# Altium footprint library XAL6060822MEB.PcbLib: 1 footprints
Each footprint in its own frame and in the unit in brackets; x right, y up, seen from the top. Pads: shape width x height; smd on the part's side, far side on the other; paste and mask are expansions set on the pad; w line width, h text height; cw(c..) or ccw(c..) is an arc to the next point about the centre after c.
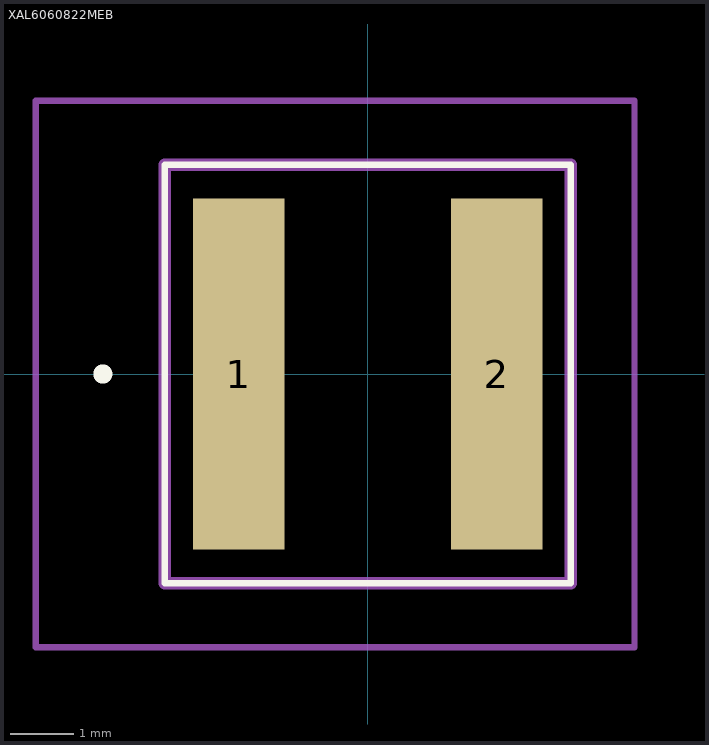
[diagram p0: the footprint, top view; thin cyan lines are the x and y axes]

## XAL6060822MEB [mm]
pads (2):
  rect 1.43x5.5 smd: 1(-2.02,0) 2(2.02,0)
Top Overlay:
  lines w0.1: -3.18,-3.28 3.18,-3.28 3.18,3.28 -3.18,3.28 -3.18,-3.28
  lines w0.2: -4.2,0 -4.2,0 ; -4.2,0 ccw(c-4.15,0) -4.1,0 ; -4.2,0 cw(c-4.15,0) -4.1,0 ; -4.2,0 -4.2,0 ; -4.2,0 ccw(c-4.15,0) -4.1,0 ; -4.1,0 -4.1,0
Mechanical 15:
  lines w0.2: -3.18,-3.28 3.18,-3.28 3.18,3.28 -3.18,3.28 -3.18,-3.28
Mechanical 20:
  lines w0.1: -5.2,-4.28 4.18,-4.28 4.18,4.28 -5.2,4.28 -5.2,-4.28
